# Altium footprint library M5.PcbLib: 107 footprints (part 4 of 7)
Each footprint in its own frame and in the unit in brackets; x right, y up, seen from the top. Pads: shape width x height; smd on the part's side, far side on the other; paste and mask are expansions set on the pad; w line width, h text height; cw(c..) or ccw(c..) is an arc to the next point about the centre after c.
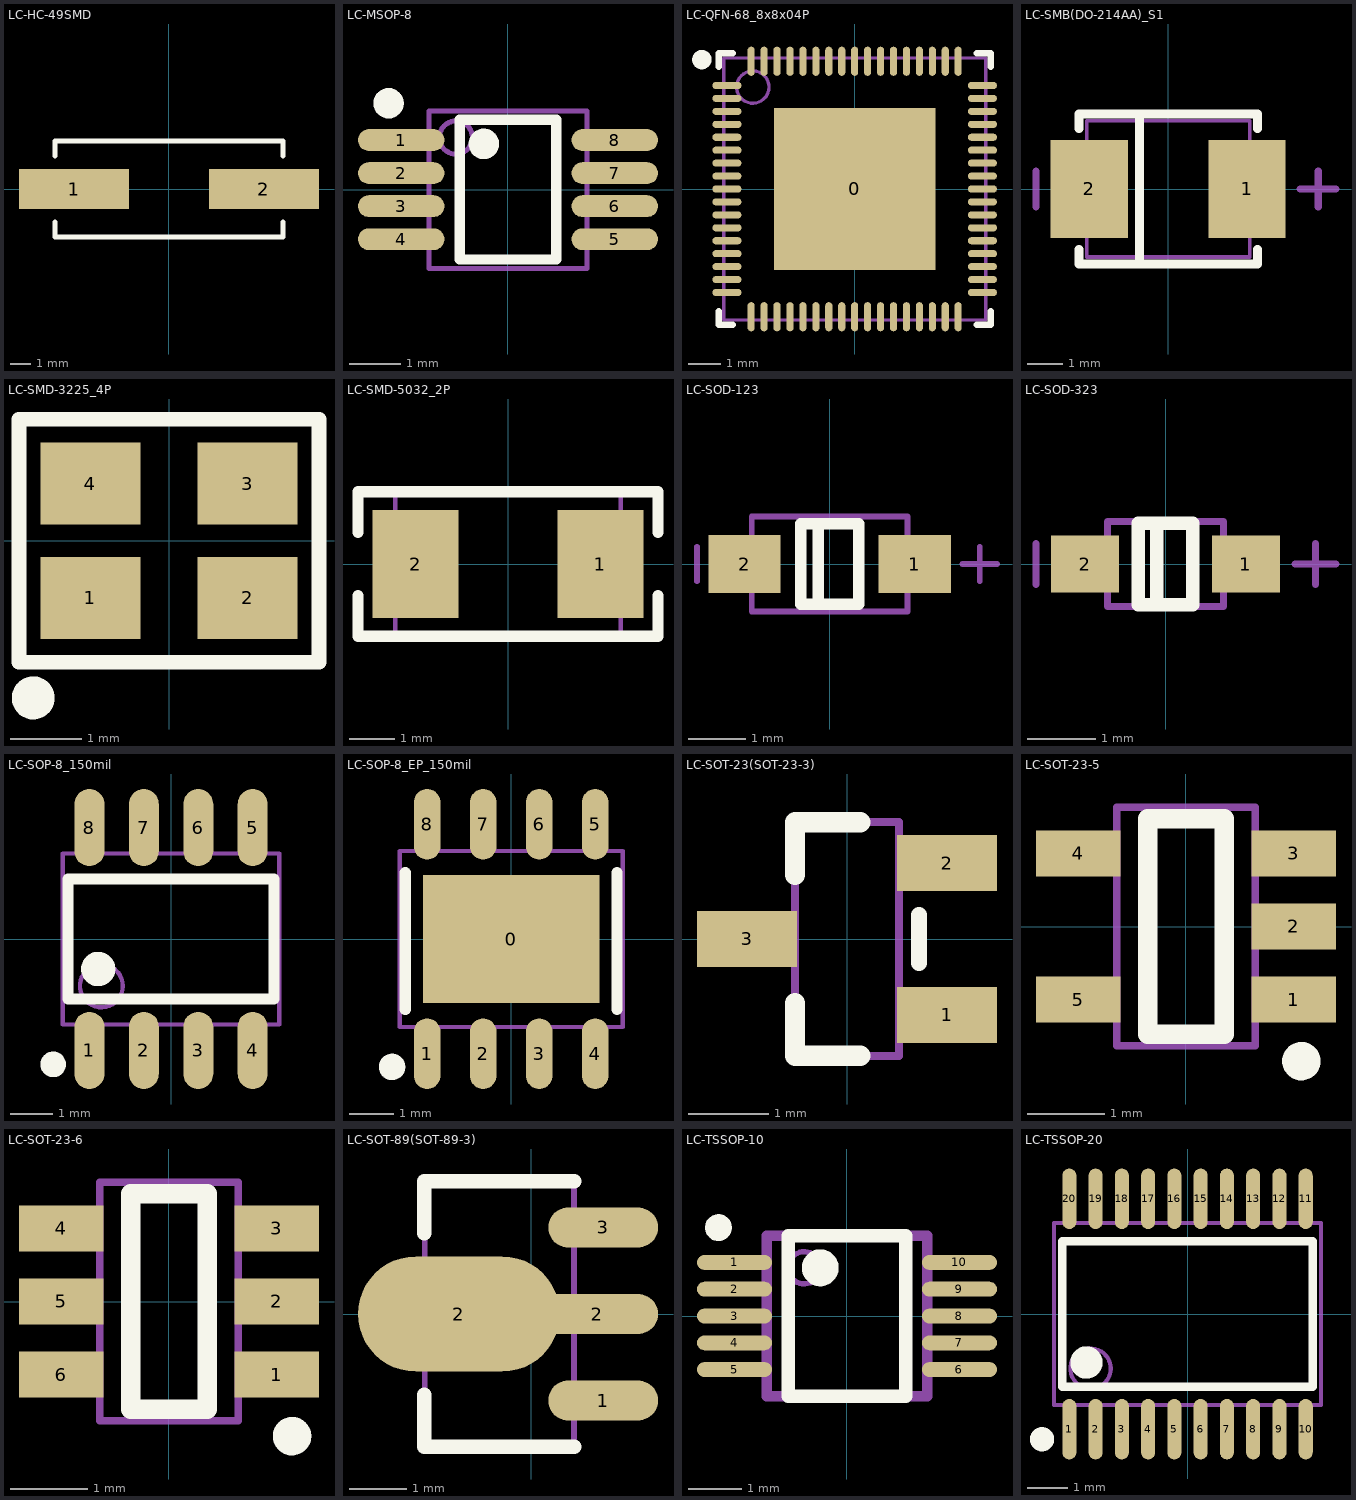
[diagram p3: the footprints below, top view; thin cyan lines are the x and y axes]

## LC-HC-49SMD [mm]
pads (2):
  rect 5.5x2 smd: 1(-4.75,0) 2(4.75,0)
Top Overlay:
  lines w0.254: -5.7,-1.65 -5.7,-2.4 5.7,-2.4 5.7,-1.65 ; -5.7,1.65 -5.7,2.4 5.7,2.4 5.7,1.65
3D body: height 4, standoff 0, extent -6.7,-2.462 6.7,2.438

## LC-MSOP-8 [mm]
pads (8):
  oval 1.7x0.43 smd mask+0.051: 1(-2.1,0.975) 2(-2.1,0.325) 3(-2.1,-0.325) 4(-2.1,-0.975) 5(2.1,-0.975) 6(2.1,-0.325) 7(2.1,0.325) 8(2.1,0.975)
Top Overlay:
  circle w0.3: c-2.35,1.7 r0.15
  circle w0.3: c-0.475,0.9 r0.15
  lines w0.2: -0.95,-1.375 -0.95,1.375 0.95,1.375 0.95,-1.375 -0.95,-1.375
Mechanical 13:
  circle w0.1: c-1.025,1.025 r0.325
  lines w0.1: -1.55,-1.55 -1.55,1.55 1.55,1.55 1.55,-1.55 -1.55,-1.55
3D body: height 0.93, standoff 0, extent -2.45,-1.5 2.45,1.5

## LC-QFN-68_8x8x04P [mm]
pads (69):
  rect 5x5 smd: 0(0,0)
  oval 0.9x0.22 smd mask+0.051: 1(-3.95,3.2) 2(-3.95,2.8) 3(-3.95,2.4) 4(-3.95,2) 5(-3.95,1.6) 6(-3.95,1.2) 7(-3.95,0.8) 8(-3.95,0.4) 9(-3.95,0) 10(-3.95,-0.4) 11(-3.95,-0.8) 12(-3.95,-1.2) 13(-3.95,-1.6) 14(-3.95,-2) 15(-3.95,-2.4) 16(-3.95,-2.8) 17(-3.95,-3.2) 35(3.95,-3.2) 36(3.95,-2.8) 37(3.95,-2.4) 38(3.95,-2) 39(3.95,-1.6) 40(3.95,-1.2) 41(3.95,-0.8) 42(3.95,-0.4) 43(3.95,0) 44(3.95,0.4) 45(3.95,0.8) 46(3.95,1.2) 47(3.95,1.6) 48(3.95,2) 49(3.95,2.4) 50(3.95,2.8) 51(3.95,3.2)
  oval 0.22x0.9 smd mask+0.051: 18(-3.2,-3.95) 19(-2.8,-3.95) 20(-2.4,-3.95) 21(-2,-3.95) 22(-1.6,-3.95) 23(-1.2,-3.95) 24(-0.8,-3.95) 25(-0.4,-3.95) 26(0,-3.95) 27(0.4,-3.95) 28(0.8,-3.95) 29(1.2,-3.95) 30(1.6,-3.95) 31(2,-3.95) 32(2.4,-3.95) 33(2.8,-3.95) 34(3.2,-3.95) 52(3.2,3.95) 53(2.8,3.95) 54(2.4,3.95) 55(2,3.95) 56(1.6,3.95) 57(1.2,3.95) 58(0.8,3.95) 59(0.4,3.95) 60(0,3.95) 61(-0.4,3.95) 62(-0.8,3.95) 63(-1.2,3.95) 64(-1.6,3.95) 65(-2,3.95) 66(-2.4,3.95) 67(-2.8,3.95) 68(-3.2,3.95)
Top Overlay:
  circle w0.3: c-4.725,4 r0.15
  lines w0.2: -4.2,-3.775 -4.2,-4.2 -3.775,-4.2 ; -4.2,3.775 -4.2,4.2 -3.775,4.2 ; 3.775,-4.2 4.2,-4.2 4.2,-3.775 ; 3.775,4.2 4.2,4.2 4.2,3.775
Mechanical 13:
  circle w0.1: c-3.15,3.15 r0.5
  lines w0.1: -4.05,-4.05 -4.05,4.05 4.05,4.05 4.05,-4.05 -4.05,-4.05
3D body: height 0.88, standoff 0, extent -3.95,-4.027 4.052,3.975

## LC-SMB(DO-214AA)_S1 [mm]
pads (2):
  rect 2.159x2.743 smd: 1(2.21,0) 2(-2.21,0)
Top Overlay:
  lines w0.254: -2.5,-1.7 -2.5,-2.1 2.5,-2.1 2.5,-1.7 ; -2.5,1.7 -2.5,2.1 2.5,2.1 2.5,1.7 ; -0.8,-2.1 -0.8,2.1
Mechanical 13:
  lines w0.1: -2.285,-1.905 -2.285,1.905 2.285,1.905 2.285,-1.905 -2.285,-1.905
Mechanical 15:
  lines w0.203: -3.7,-0.5 -3.7,0.5 ; 3.7,0 4.7,0 ; 4.2,-0.5 4.2,0.5
3D body: height 2.35, standoff 0.04, extent -2.779,-1.8 2.525,1.8

## LC-SMD-3225_4P [mm]
pads (4):
  rect 1.4x1.15 smd: 1(-1.1,-0.8) 2(1.1,-0.8) 3(1.1,0.8) 4(-1.1,0.8)
Top Overlay:
  circle w0.3: c-1.9,-2.2 r0.15
  lines w0.203: -2.1,-1.7 2.1,-1.7 2.1,1.7 -2.1,1.7 -2.1,-1.7
3D body: height 0.61, standoff 0, extent -1.6,-1.25 1.6,1.25

## LC-SMD-5032_2P [mm]
pads (2):
  rect 1.9x2.4 smd: 1(2.05,0) 2(-2.05,0)
Top Overlay:
  lines w0.254: -3.325,-0.7 -3.325,-1.6 3.325,-1.6 3.325,-0.7 ; -3.325,0.7 -3.325,1.6 3.325,1.6 3.325,0.7
Mechanical 13:
  lines w0.1: -2.5,-1.6 -2.5,1.6 2.5,1.6 2.5,-1.6 -2.5,-1.6
3D body: height 0.86, standoff 0.04, extent -2.5,-1.727 2.5,1.473

## LC-SOD-123 [mm]
pads (2):
  rect 1.25x1 smd: 1(1.475,0) 2(-1.475,0)
Top Overlay:
  lines w0.2: -0.2,-0.7 -0.2,0.7 ; -0.5,-0.7 -0.5,0.7 0.5,0.7 0.5,-0.7 -0.5,-0.7
Mechanical 13:
  lines w0.1: -1.35,-0.825 1.35,-0.825 1.35,0.825 -1.35,0.825 -1.35,-0.825
Mechanical 15:
  lines w0.1: -2.3,-0.3 -2.3,0.3 ; 2.3,0 2.9,0 ; 2.6,-0.3 2.6,0.3
3D body: height 1.35, standoff 0, extent -1.85,-0.775 1.85,0.775

## LC-SOD-323 [mm]
pads (2):
  rect 1x0.83 smd: 1(1.18,0) 2(-1.18,0)
Top Overlay:
  lines w0.2: -0.13,-0.6 -0.13,0.6 ; -0.4,-0.6 0.4,-0.6 0.4,0.6 -0.4,0.6 -0.4,-0.6
Mechanical 13:
  lines w0.1: -0.85,-0.625 0.85,-0.625 0.85,0.625 -0.85,0.625 -0.85,-0.625
Mechanical 15:
  lines w0.1: -1.9,-0.3 -1.9,0.3 ; 1.9,0 2.5,0 ; 2.2,-0.3 2.2,0.3
3D body: height 1.1, standoff 0, extent -1.35,-0.625 1.35,0.625

## LC-SOP-8_150mil [mm]
pads (8):
  oval 0.7x1.8 smd: 1(-1.905,-2.6) 2(-0.635,-2.6) 3(0.635,-2.6) 4(1.905,-2.6) 5(1.905,2.6) 6(0.635,2.6) 7(-0.635,2.6) 8(-1.905,2.6)
Top Overlay:
  circle w0.3: c-2.75,-2.925 r0.15
  circle w0.4: c-1.7,-0.7 r0.2
  lines w0.254: -2.4,-1.4 2.4,-1.4 2.4,1.4 -2.4,1.4 -2.4,-1.4
Mechanical 13:
  circle w0.1: c-1.625,-1.095 r0.5
  lines w0.1: -2.525,-1.995 2.525,-1.995 2.525,1.995 -2.525,1.995 -2.525,-1.995
3D body: height 1.87, standoff 0, extent -2.5,-3.11 2.5,3.11

## LC-SOP-8_EP_150mil [mm]
pads (9):
  rect 4x2.9 smd: 0(0,0)
  oval 0.6x1.6 smd: 1(-1.905,-2.6) 2(-0.635,-2.6) 3(0.635,-2.6) 4(1.905,-2.6) 5(1.905,2.6) 6(0.635,2.6) 7(-0.635,2.6) 8(-1.905,2.6)
Top Overlay:
  circle w0.3: c-2.7,-2.9 r0.15
  lines w0.254: -2.4,-1.6 -2.4,1.5 ; 2.4,-1.6 2.4,1.5
Mechanical 13:
  lines w0.1: -2.525,-1.995 2.525,-1.995 2.525,1.995 -2.525,1.995 -2.525,-1.995
3D body: height 1.87, standoff 0, extent -2.46,-3.11 2.54,3.11

## LC-SOT-23(SOT-23-3) [mm]
pads (3):
  rect 1.25x0.7 smd: 1(1.25,-0.95) 2(1.25,0.95) 3(-1.25,0)
Top Overlay:
  lines w0.2: 0.9,-0.3 0.9,0.3
  lines w0.254: -0.65,-0.8 -0.65,-1.46 0.165,-1.46 ; 0.165,1.46 -0.65,1.46 ; -0.65,0.8 -0.65,1.46 ; -0.65,0.8 -0.65,1.46 ; -0.65,0.8 -0.65,1.46
Mechanical 13:
  lines w0.1: -0.65,-1.46 0.65,-1.46 ; -0.65,-1.46 0.65,-1.46 ; -0.65,-1.46 0.65,-1.46 ; -0.65,-1.46 -0.65,1.46 ; -0.65,-1.46 -0.65,1.46 ; -0.65,-1.46 -0.65,1.46 ; -0.65,1.46 0.65,1.46 ; -0.65,1.46 0.65,1.46 ; -0.65,1.46 0.65,1.46 ; 0.65,-1.46 0.65,1.46 ; 0.65,-1.46 0.65,1.46 ; 0.65,-1.46 0.65,1.46
3D body: height 1.3, standoff 0, extent -1.5,-1.5 1.5,1.5

## LC-SOT-23-5 [mm]
pads (5):
  rect 1.1x0.6 smd: 1(1.4,-0.95) 2(1.4,0) 3(1.4,0.95) 4(-1.4,0.95) 5(-1.4,-0.95)
Top Overlay:
  circle w0.25: c1.5,-1.75 r0.125
  lines w0.254: -0.5,-1.4 -0.5,1.4 0.5,1.4 0.5,-1.4 -0.5,-1.4
Mechanical 13:
  lines w0.1: -0.9,-1.55 0.9,-1.55 0.9,1.55 -0.9,1.55 -0.9,-1.55
3D body: height 1.06, standoff -0.04, extent -1.25,-1.5 1.25,1.5

## LC-SOT-23-6 [mm]
pads (6):
  rect 1.1x0.6 smd: 1(1.4,-0.95) 2(1.4,0) 3(1.4,0.95) 4(-1.4,0.95) 5(-1.4,0) 6(-1.4,-0.95)
Top Overlay:
  circle w0.25: c1.6,-1.75 r0.125
  lines w0.254: -0.5,-1.4 -0.5,1.4 0.5,1.4 0.5,-1.4 -0.5,-1.4
Mechanical 13:
  lines w0.1: -0.9,-1.55 -0.9,1.55 0.9,1.55 0.9,-1.55 -0.9,-1.55
3D body: height 1, standoff 0, extent -1.17,-1.46 1.17,1.46

## LC-SOT-89(SOT-89-3) [mm]
pads (4):
  oval 1.9x0.7 smd: 1(1.25,-1.5) 3(1.25,1.5)
  oval 3.5x2 smd: 2(-1.25,0)
  oval 2.1x0.7 smd: 2(1.15,0)
Top Overlay:
  lines w0.254: -1.85,-1.4 -1.85,-2.3 0.75,-2.3 ; -1.85,1.4 -1.85,2.3 0.75,2.3
Mechanical 13:
  lines w0.1: -1.845,-2.3 0.745,-2.3 0.745,2.3 -1.845,2.3 -1.845,-2.3
3D body: height 1.51, standoff 0, extent -2.5,-2.25 1.8,2.25

## LC-TSSOP-10 [mm]
pads (10):
  oval 1.4x0.28 smd mask+0.051: 1(-2.1,1) 2(-2.1,0.5) 3(-2.1,0) 4(-2.1,-0.5) 5(-2.1,-1) 6(2.1,-1) 7(2.1,-0.5) 8(2.1,0) 9(2.1,0.5) 10(2.1,1)
Top Overlay:
  circle w0.25: c-2.4,1.65 r0.125
  circle w0.35: c-0.5,0.9 r0.17
  lines w0.254: -1.1,-1.5 1.1,-1.5 1.1,1.5 -1.1,1.5 -1.1,-1.5
Mechanical 13:
  circle w0.1: c-0.8,0.9 r0.3
  lines w0.2: -1.5,-1.5 -1.5,1.5 1.5,1.5 1.5,-1.5 -1.5,-1.5
3D body: height 1.1, standoff 0, extent -2.45,-1.5 2.45,1.5

## LC-TSSOP-20 [mm]
pads (20):
  oval 0.35x1.5 smd: 1(-2.925,-2.85) 2(-2.275,-2.85) 3(-1.625,-2.85) 4(-0.975,-2.85) 5(-0.325,-2.85) 6(0.325,-2.85) 7(0.975,-2.85) 8(1.625,-2.85) 9(2.275,-2.85) 10(2.925,-2.85) 11(2.925,2.85) 12(2.275,2.85) 13(1.625,2.85) 14(0.975,2.85) 15(0.325,2.85) 16(-0.325,2.85) 17(-0.975,2.85) 18(-1.625,2.85) 19(-2.275,2.85) 20(-2.925,2.85)
Top Overlay:
  circle w0.4: c-2.5,-1.2 r0.2
  circle w0.3: c-3.6,-3.1 r0.15
  lines w0.2: -3.1,-1.8 3.1,-1.8 3.1,1.8 -3.1,1.8 -3.1,-1.8
Mechanical 13:
  circle w0.1: c-2.4,-1.35 r0.5
  lines w0.1: -3.3,-2.25 3.3,-2.25 3.3,2.25 -3.3,2.25 -3.3,-2.25
3D body: height 1.1, standoff 0, extent -3.25,-3.2 3.25,3.2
